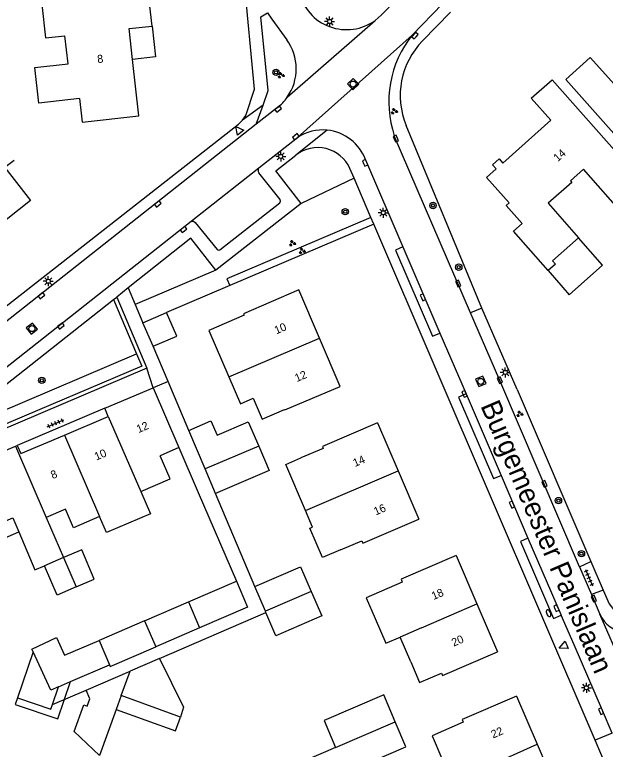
# Model space of a CAD drawing. Extents: x 136000 to 138005, y 398500 to 400500.
# Drawn here: x 137735.1 to 137809, y 398782 to 398873.8 of the extents above; entities that cross this region are included whole.
import ezdxf

# ---------------------------------------------------------------- set-up
doc = ezdxf.new("R2010")
doc.units = 0
for name, color, linetype in [('gg-afsc-erfafscheiding', 7, 'Continuous'), ('gg-afsc-hekwerk', 7, 'Continuous'), ('gg-afsc-muur', 7, 'Continuous'), ('gg-anno-huisnummerreeks BGT', 7, 'Continuous'), ('gg-anno-openbare ruimte label', 7, 'Continuous'), ('gg-bbg-bijgebouw', 7, 'Continuous'), ('gg-bbg-gedigitaliseerde bebouwing', 7, 'Continuous'), ('gg-bbg-gedigitaliseerde bijgebouw', 7, 'Continuous'), ('gg-bbg-hoofdgebouw', 7, 'Continuous'), ('gg-bbg-luifel en loopbrug', 7, 'Continuous'), ('gg-bbg-tussenscheiding', 7, 'Continuous'), ('gg-knt-verharding', 7, 'Continuous'), ('gg-knt-verharding nz', 7, 'Continuous'), ('gt-grn-groengrens', 7, 'Continuous'), ('gt-grn-weggrens', 7, 'Continuous'), ('gt-symb-boom', 7, 'Continuous'), ('gt-symb-brandkraan', 7, 'Continuous'), ('gt-symb-groenvak', 7, 'Continuous'), ('gt-symb-kolk', 7, 'Continuous'), ('gt-symb-lichtmast', 7, 'Continuous'), ('gt-symb-rioolschacht', 7, 'Continuous'), ('gt-symb-tegel verharding', 7, 'Continuous'), ('gt-symb-waterafsluiter', 7, 'Continuous')]:
    doc.layers.add(name, color=color, linetype=linetype)

# ---------------------------------------------------------------- blocks, each defined once
blk = doc.blocks.new('gt0-WAFSL')
at = {"layer": 'gt-symb-waterafsluiter'}
for p, q in [((-0.5, -0.333), (0, 0.667)), ((0, 0.667), (0.5, -0.333)), ((0.5, -0.333), (-0.5, -0.333))]:
    blk.add_line(p, q, dxfattribs=at)
blk = doc.blocks.new('gt0-GRVAK')
at = {"layer": 'gt-symb-groenvak'}
for p, q in [((-0.11, 0.189), (-0.228, 0.24)), ((-0.182, 0.153), (0.088, 0.153)), ((-0.091, 0.211), (-0.156, 0.322)), ((-0.047, 0.214), (-0.047, 0.393)), ((-0.004, 0.211), (0.061, 0.322)), ((0.015, 0.189), (0.133, 0.24)), ((0.262, -0.052), (0.197, 0.059)), ((0.305, -0.049), (0.305, 0.13)), ((0.349, -0.052), (0.414, 0.059)), ((-0.245, -0.228), (-0.363, -0.177)), ((-0.318, -0.264), (-0.047, -0.264)), ((-0.226, -0.206), (-0.291, -0.095)), ((-0.183, -0.203), (-0.183, -0.024)), ((-0.139, -0.206), (-0.074, -0.095)), ((-0.12, -0.228), (-0.002, -0.177)), ((0.243, -0.074), (0.125, -0.023)), ((0.17, -0.11), (0.441, -0.11)), ((0.368, -0.074), (0.486, -0.023))]:
    blk.add_line(p, q, dxfattribs=at)
blk = doc.blocks.new('gt0-KOLK')
at = {"layer": 'gt-symb-kolk'}
blk.add_lwpolyline([(0, 0), (0.375, 0), (0.375, 0.4), (-0.375, 0.4), (-0.375, 0), (0, 0)], dxfattribs=at)
blk = doc.blocks.new('gt0-RS')
at = {"layer": 'gt-symb-rioolschacht'}
blk.add_lwpolyline([(-0.5, -0.5), (0.5, -0.5), (0.5, 0.5), (-0.5, 0.5)], close=True, dxfattribs=at)
blk.add_circle((0, 0), 0.375, dxfattribs=at)
blk = doc.blocks.new('gt0-BOOM')
at = {"layer": 'gt-symb-boom'}
for radius in [0.4, 0.2]:
    blk.add_circle((0, 0), radius, dxfattribs=at)
blk = doc.blocks.new('gt0-LMAST')
at = {"layer": 'gt-symb-lichtmast'}
for p, q in [((-0.182, 0.173), (-0.447, 0.438)), ((-0.005, 0.246), (-0.005, 0.621)), ((0.172, 0.173), (0.437, 0.438)), ((-0.255, -0.004), (-0.63, -0.004)), ((-0.182, -0.181), (-0.447, -0.446)), ((-0.005, -0.254), (-0.005, -0.629)), ((0.437, -0.446), (0.172, -0.181)), ((0.245, -0.004), (0.62, -0.004))]:
    blk.add_line(p, q, dxfattribs=at)
blk.add_circle((-0.005, -0.004), 0.25, dxfattribs=at)
blk = doc.blocks.new('gt0-TEG1')
at = {"layer": 'gt-symb-tegel verharding'}
for p, q in [((-1.125, 0), (1.125, 0)), ((-0.9, -0.25), (-0.9, 0.25)), ((-0.45, -0.25), (-0.45, 0.25)), ((0, -0.25), (0, 0.25)), ((0.45, -0.25), (0.45, 0.25)), ((0.9, -0.25), (0.9, 0.25))]:
    blk.add_line(p, q, dxfattribs=at)
blk = doc.blocks.new('gt0-BR')
at = {"layer": 'gt-symb-brandkraan'}
for centre, radius, start, end in [((-0.244, 0), 0.206, 107.56694, 252.43307), ((0.599, -2.664), 3, 106.89205, 107.56694), ((0, -0.691), 0.938, 73.10799, 106.89205), ((-0.599, -2.664), 3, 72.43309, 73.10799), ((0.244, 0), 0.206, 287.56695, 72.43309), ((0.599, 2.664), 3, 252.43307, 253.10797), ((0, 0.691), 0.938, 253.10797, 286.89206), ((-0.599, 2.664), 3, 286.89206, 287.56695)]:
    blk.add_arc(centre, radius, start, end, dxfattribs=at)

msp = doc.modelspace()

# ---------------------------------------------------------------- linework, layer by layer
at = {"layer": 'gg-afsc-erfafscheiding'}
for p, q in [((137780.034, 398847.619), (137762.017, 398839.982)), ((137758.08, 398814.098), (137762.846, 398803.03)), ((137765.162, 398802.336), (137760.232, 398813.97)), ((137753.222, 398793.371), (137766.53, 398799.12)), ((137739.843, 398787.592), (137744.064, 398789.415))]:
    msp.add_line(p, q, dxfattribs=at)
at = {"layer": 'gg-afsc-hekwerk'}
for p, q in [((137797.931, 398826.979), (137807.16, 398805.464)), ((137807.16, 398805.464), (137808.684, 398801.91))]:
    msp.add_line(p, q, dxfattribs=at)
msp.add_lwpolyline([(137808.684, 398801.91), (137809.432, 398800.189), (137810.149, 398799.284), (137811.65, 398798.236), (137813.481, 398798.666), (137827.526, 398808.434)], dxfattribs=at)
at = {"layer": 'gg-afsc-muur'}
for p, q in [((137762.017, 398839.982), (137754.121, 398836.573)), ((137754.313, 398827.975), (137752.443, 398832.372)), ((137756.912, 398821.866), (137754.313, 398827.975)), ((137755.641, 398819.704), (137758.08, 398814.098))]:
    msp.add_line(p, q, dxfattribs=at)
at = {"layer": 'gg-bbg-bijgebouw'}
for p, q in [((137751.165, 398835.297), (137754.121, 398836.573)), ((137752.443, 398832.372), (137751.165, 398835.297)), ((137758.926, 398817.077), (137756.912, 398821.866)), ((137760.232, 398813.97), (137758.926, 398817.077)), ((137762.846, 398803.03), (137764.23, 398799.784))]:
    msp.add_line(p, q, dxfattribs=at)
at = {"layer": 'gg-bbg-gedigitaliseerde bebouwing'}
for p, q in [((137743.239, 398863.336), (137743.56, 398860.38)), ((137805.625, 398845.904), (137802.36, 398843.03)), ((137759.4, 398834.34), (137761.906, 398828.559)), ((137755.641, 398819.704), (137753.294, 398818.691)), ((137739.056, 398810.977), (137741.214, 398805.968)), ((137745.726, 398811.111), (137742.459, 398809.701)), ((137775.857, 398806.931), (137773.619, 398805.97)), ((137784.635, 398792.952), (137783.311, 398796.036))]:
    msp.add_line(p, q, dxfattribs=at)
for points in [[(137751.83, 398876.57), (137738.539, 398875.069), (137738.989, 398870.908), (137741.416, 398871.17)], [(137743.239, 398863.336), (137738.138, 398862.754), (137737.632, 398867.185), (137741.816, 398867.662), (137741.416, 398871.17)], [(137811.458, 398848.583), (137806.241, 398854.497), (137804.599, 398853.048), (137804.771, 398852.853), (137801.806, 398850.243), (137805.625, 398845.904)], [(137761.906, 398828.559), (137763.367, 398825.19), (137764.956, 398825.869), (137766.061, 398823.281), (137768.868, 398824.48), (137768.896, 398824.414), (137775.81, 398827.36)], [(137780.49, 398822.82), (137773.588, 398819.858), (137773.692, 398819.615), (137770.901, 398818.418)], [(137750.896, 398814.218), (137754.545, 398815.793), (137753.294, 398818.691)], [(137771.484, 398811.832), (137769.006, 398817.604), (137770.901, 398818.418)], [(137730.896, 398813.965), (137732.603, 398809.96), (137734.903, 398810.937), (137735.645, 398809.191)], [(137750.896, 398814.218), (137752.108, 398811.428), (137746.6, 398809.089), (137745.726, 398811.111)], [(137742.459, 398809.701), (137741.463, 398812.014), (137739.056, 398810.977)], [(137773.619, 398805.97), (137772.042, 398809.646), (137772.363, 398809.784), (137771.484, 398811.832)], [(137775.857, 398806.931), (137778.533, 398808.079), (137778.664, 398807.774), (137785.66, 398810.77)], [(137735.645, 398809.191), (137737.661, 398804.445), (137738.864, 398804.956)], [(137790.3, 398806.23), (137783.423, 398803.264), (137783.584, 398802.891), (137779.061, 398800.946), (137780.176, 398798.352)], [(137780.176, 398798.352), (137781.505, 398795.257), (137783.311, 398796.036)], [(137784.635, 398792.952), (137785.744, 398790.373), (137788.466, 398791.544), (137788.607, 398791.215), (137795.48, 398794.18)], [(137797.85, 398788.67), (137791.048, 398785.736), (137791.199, 398785.383), (137787.301, 398783.709), (137788.523, 398780.863)]]:
    msp.add_lwpolyline(points, dxfattribs=at)
at = {"layer": 'gg-bbg-gedigitaliseerde bijgebouw'}
for p, q in [((137756.848, 398800.441), (137762.846, 398803.03)), ((137766.468, 398799.266), (137765.162, 398802.336)), ((137751.356, 398798.07), (137756.848, 398800.441)), ((137764.23, 398799.784), (137758.246, 398797.201)), ((137766.53, 398799.12), (137766.468, 398799.266)), ((137751.356, 398798.07), (137745.671, 398795.616)), ((137758.246, 398797.201), (137752.754, 398794.83)), ((137747.069, 398792.376), (137752.754, 398794.83)), ((137737.422, 398794.197), (137735.475, 398788.432)), ((137742.108, 398790.483), (137746.979, 398792.586)), ((137746.979, 398792.586), (137747.069, 398792.376)), ((137753.222, 398793.371), (137749.552, 398791.786)), ((137744.064, 398789.415), (137749.552, 398791.786)), ((137739.843, 398787.592), (137740.599, 398789.832)), ((137740.599, 398789.832), (137742.108, 398790.483)), ((137744.531, 398788.335), (137744.064, 398789.415)), ((137748.442, 398788.729), (137747.812, 398786.995)), ((137755.851, 398786.038), (137748.442, 398788.729))]:
    msp.add_line(p, q, dxfattribs=at)
for points in [[(137752.443, 398832.372), (137755.386, 398833.643), (137754.121, 398836.573)], [(137756.912, 398821.866), (137759.659, 398823.052), (137760.437, 398821.249), (137764.321, 398822.926), (137765.629, 398819.896)], [(137765.629, 398819.896), (137766.937, 398816.865), (137760.232, 398813.97)], [(137742.794, 398802.301), (137745.082, 398803.286), (137743.503, 398806.954), (137741.214, 398805.968)], [(137742.794, 398802.301), (137740.444, 398801.289), (137738.864, 398804.956)], [(137765.162, 398802.336), (137770.873, 398804.801), (137772.195, 398801.739)], [(137772.195, 398801.739), (137773.517, 398798.676), (137767.789, 398796.204), (137766.53, 398799.12)], [(137737.422, 398794.197), (137737.264, 398794.535), (137740.334, 398795.969), (137741.366, 398793.758), (137745.671, 398795.616)], [(137753.222, 398793.371), (137756.251, 398787.276), (137755.851, 398786.038)], [(137735.475, 398788.432), (137739.651, 398787.022), (137739.843, 398787.592)], [(137742.547, 398784.251), (137743.772, 398787.554), (137744.184, 398787.401), (137744.531, 398788.335)], [(137782.706, 398785.439), (137781.257, 398788.813), (137773.798, 398785.611), (137775.254, 398782.22)], [(137747.812, 398786.995), (137745.715, 398781.223), (137742.547, 398784.251)], [(137775.254, 398782.22), (137767.044, 398778.695), (137768.378, 398775.589), (137784.046, 398782.317), (137782.706, 398785.439)]]:
    msp.add_lwpolyline(points, dxfattribs=at)
at = {"layer": 'gg-bbg-hoofdgebouw'}
for p, q in [((137752.31, 398872.36), (137751.83, 398876.57)), ((137775.81, 398827.36), (137773.235, 398833.39)), ((137746.4, 398824.62), (137752.42, 398827.17)), ((137752.42, 398827.17), (137755.641, 398819.704)), ((137746.82, 398823.6), (137746.4, 398824.62)), ((137741.34, 398821.272), (137746.82, 398823.6)), ((137780.49, 398822.82), (137783.075, 398816.795)), ((137730.838, 398818.033), (137735.214, 398819.894)), ((137735.214, 398819.894), (137735.44, 398819.99)), ((137783.075, 398816.795), (137785.66, 398810.77)), ((137790.3, 398806.23), (137792.89, 398800.205)), ((137792.89, 398800.205), (137795.48, 398794.18)), ((137797.85, 398788.67), (137800.44, 398782.64)), ((137800.44, 398782.64), (137803.03, 398776.61))]:
    msp.add_line(p, q, dxfattribs=at)
for points in [[(137749.867, 398868.205), (137749.45, 398872.06), (137752.31, 398872.36)], [(137743.56, 398860.38), (137750.63, 398861.15), (137749.867, 398868.205)], [(137802.32, 398865.68), (137811.687, 398855.096), (137812.677, 398855.973), (137804.031, 398865.719), (137807.085, 398868.469), (137819.213, 398855.006), (137816.037, 398852.145), (137815.337, 398852.927), (137814.369, 398852.06)], [(137801.82, 398841.82), (137797.48, 398846.75), (137798.56, 398847.72), (137796.58, 398849.97), (137796.94, 398850.28), (137794.1, 398853.46), (137795.31, 398854.54), (137794.85, 398855.05), (137795.69, 398855.8), (137796.15, 398855.27), (137802.15, 398860.64), (137799.71, 398863.37), (137802.32, 398865.68)], [(137735.05, 398855.59), (137733.9, 398854.69), (137737.11, 398850.59), (137731.172, 398845.934)], [(137802.36, 398843.03), (137802.73, 398842.61), (137801.82, 398841.82)], [(137773.235, 398833.39), (137770.66, 398839.42), (137763.73, 398836.43), (137763.83, 398836.25), (137759.4, 398834.34)], [(137735.44, 398819.99), (137735.9, 398818.96), (137741.34, 398821.272)]]:
    msp.add_lwpolyline(points, dxfattribs=at)
at = {"layer": 'gg-bbg-luifel en loopbrug'}
msp.add_line((137731.538, 398807.423), (137735.645, 398809.191), dxfattribs=at)
for points in [[(137752.31, 398872.36), (137752.746, 398868.534), (137749.867, 398868.205)], [(137801.82, 398841.82), (137804.463, 398838.818), (137808.632, 398842.488), (137805.625, 398845.904)], [(137735.475, 398788.432), (137735.204, 398787.63), (137740.536, 398785.829), (137742.108, 398790.483)], [(137747.812, 398786.995), (137755.221, 398784.304), (137755.851, 398786.038)]]:
    msp.add_lwpolyline(points, dxfattribs=at)
at = {"layer": 'gg-bbg-tussenscheiding'}
for p, q in [((137761.906, 398828.559), (137773.235, 398833.39)), ((137746.82, 398823.6), (137750.896, 398814.218)), ((137741.34, 398821.272), (137745.726, 398811.111)), ((137735.214, 398819.894), (137739.056, 398810.977)), ((137765.629, 398819.896), (137758.926, 398817.077)), ((137771.484, 398811.832), (137783.075, 398816.795)), ((137741.214, 398805.968), (137738.864, 398804.956)), ((137741.214, 398805.968), (137742.794, 398802.301)), ((137772.195, 398801.739), (137766.468, 398799.266)), ((137756.848, 398800.441), (137758.246, 398797.201)), ((137785.989, 398797.192), (137792.89, 398800.205)), ((137751.356, 398798.07), (137752.754, 398794.83)), ((137785.989, 398797.192), (137783.311, 398796.036)), ((137745.671, 398795.616), (137746.979, 398792.586)), ((137748.442, 398788.729), (137749.552, 398791.786)), ((137775.254, 398782.22), (137782.706, 398785.439)), ((137793.711, 398779.646), (137800.44, 398782.64))]:
    msp.add_line(p, q, dxfattribs=at)
msp.add_lwpolyline([(137740.599, 398789.832), (137739.652, 398789.422), (137737.422, 398794.197)], dxfattribs=at)
at = {"layer": 'gg-knt-verharding'}
for p, q in [((137784.811, 398871.263), (137788.615, 398875.153)), ((137765.325, 398860.104), (137766.172, 398862.515)), ((137767.979, 398862.202), (137765.325, 398860.104)), ((137763.625, 398860.627), (137764.04, 398861.22)), ((137765.325, 398860.104), (137696.173, 398805.626)), ((137792.122, 398836.535), (137782.584, 398858.67)), ((137765.649, 398854.652), (137770.469, 398858.451)), ((137778.995, 398855.661), (137783.668, 398844.778)), ((137777.555, 398853.394), (137777.042, 398854.59)), ((137779.668, 398848.471), (137777.555, 398853.394)), ((137770.928, 398850.204), (137760.288, 398841.873)), ((137700.598, 398803.386), (137757.205, 398847.998)), ((137780.034, 398847.619), (137779.668, 398848.471)), ((137787.829, 398829.458), (137780.034, 398847.619)), ((137783.668, 398844.778), (137788.285, 398834.027)), ((137749.3, 398839.66), (137750.192, 398837.574)), ((137747.473, 398838.2), (137747.88, 398838.52)), ((137747.88, 398838.52), (137751.66, 398829.63)), ((137728.586, 398823.329), (137747.473, 398838.2)), ((137750.192, 398837.574), (137751.165, 398835.297)), ((137788.285, 398834.027), (137791.55, 398826.424)), ((137751.66, 398829.63), (137729.85, 398820.355)), ((137807.709, 398783.153), (137787.829, 398829.458)), ((137791.55, 398826.424), (137795.923, 398816.242)), ((137795.923, 398816.242), (137799.297, 398808.384)), ((137799.297, 398808.384), (137803.434, 398798.76)), ((137805.734, 398804.823), (137807.16, 398805.464)), ((137805.734, 398804.823), (137807.217, 398801.365)), ((137808.684, 398801.91), (137807.217, 398801.365)), ((137807.217, 398801.365), (137808.279, 398798.887)), ((137860.962, 398659.111), (137807.709, 398783.153))]:
    msp.add_line(p, q, dxfattribs=at)
for points in [[(137764.04, 398861.22), (137765.126, 398864.476), (137762.521, 398891.862), (137760.686, 398913.953)], [(137816.396, 398909.991), (137780.932, 398873.722), (137780.577, 398873.393), (137780.195, 398873.092)], [(137766.172, 398862.515), (137766.804, 398864.317), (137765.913, 398873.55), (137766.744, 398874.046)], [(137766.744, 398874.046), (137767.262, 398873.24), (137769.134, 398870.678)], [(137695.033, 398806.84), (137763.09, 398860.14), (137763.625, 398860.627)], [(137770.928, 398850.204), (137767.756, 398854.274), (137770.269, 398856.265)], [(137757.205, 398847.998), (137757.481, 398847.998), (137757.709, 398847.844), (137760.427, 398844.458), (137760.592, 398844.367), (137760.773, 398844.418), (137768.271, 398850.301), (137768.376, 398850.486), (137768.318, 398850.691), (137765.658, 398854.05)], [(137760.288, 398841.873), (137757.131, 398845.861), (137749.3, 398839.66)], [(137805.734, 398804.823), (137795.637, 398828.377), (137792.122, 398836.535)], [(137809.804, 398784.049), (137808.608, 398786.846), (137805.069, 398795.057), (137803.434, 398798.76)]]:
    msp.add_lwpolyline(points, dxfattribs=at)
for centre, radius, start, end in [((137776.615, 398878.023), 6.093, 193.41717, 305.98014), ((137764.153, 398867.04), 6.168, 324.76261, 36.14493), ((137795.316, 398862.912), 13.42, 141.51534, 198.42717), ((137764.156, 398867.039), 6.165, 308.32511, 324.7563), ((137773.627, 398853.682), 5.72, 84.25869, 123.51), ((137773.628, 398853.681), 5.72, 20.2483, 84.27351), ((137772.993, 398852.747), 4.449, 24.47524, 127.74306), ((137766.044, 398854.357), 0.493, 143.2434, 218.46964), ((137811.783, 398800.431), 3.829, 203.7767, 265.05578)]:
    msp.add_arc(centre, radius, start, end, dxfattribs=at)
at = {"layer": 'gg-knt-verharding nz'}
msp.add_line((137757.205, 398847.998), (137765.649, 398854.652), dxfattribs=at)
for points in [[(137783.668, 398844.778), (137782.744, 398844.381), (137787.353, 398833.626), (137788.285, 398834.027)], [(137791.55, 398826.424), (137790.601, 398826.016), (137794.973, 398815.834), (137795.923, 398816.242)], [(137799.297, 398808.384), (137798.347, 398807.976), (137802.491, 398798.344), (137803.434, 398798.76)]]:
    msp.add_lwpolyline(points, dxfattribs=at)
at = {"layer": 'gt-grn-groengrens'}
for p, q in [((137786.113, 398870.525), (137789.624, 398874.098)), ((137793.543, 398837.147), (137784.068, 398859.951)), ((137777.555, 398853.394), (137770.928, 398850.204)), ((137760.288, 398841.873), (137750.192, 398837.574)), ((137747.473, 398838.2), (137750.35, 398831.432)), ((137793.543, 398837.147), (137792.122, 398836.535)), ((137797.931, 398826.979), (137793.543, 398837.147)), ((137729.02, 398822.308), (137750.35, 398831.432)), ((137750.35, 398831.432), (137751.004, 398829.894)), ((137751.004, 398829.894), (137729.654, 398820.815))]:
    msp.add_line(p, q, dxfattribs=at)
msp.add_lwpolyline([(137779.668, 398848.471), (137761.668, 398840.79), (137762.017, 398839.982)], dxfattribs=at)
msp.add_arc((137793.076, 398863.694), 9.755, 135.5476, 202.56079, dxfattribs=at)
at = {"layer": 'gt-grn-weggrens'}
for p, q in [((137769.191, 398863.481), (137780.195, 398873.092)), ((137784.811, 398871.263), (137770.469, 398858.451)), ((137766.172, 398862.515), (137763.625, 398860.627)), ((137774.199, 398859.373), (137770.269, 398856.265)), ((137749.3, 398839.66), (137747.88, 398838.52)), ((137752.42, 398827.17), (137751.66, 398829.63)), ((137754.313, 398827.975), (137752.42, 398827.17)), ((137746.4, 398824.62), (137735.44, 398819.99)), ((137813.949, 398785.823), (137808.279, 398798.887)), ((137809.804, 398784.049), (137807.709, 398783.153))]:
    msp.add_line(p, q, dxfattribs=at)

# ---------------------------------------------------------------- block references
at = {"layer": 'gt-symb-boom'}
for p in [(137767.795, 398866.6), (137776.453, 398849.184), (137787.425, 398849.958), (137790.641, 398842.256), (137738.52, 398828.114), (137803.107, 398813.086), (137805.978, 398806.457)]:
    msp.add_blockref('gt0-BOOM', p, dxfattribs=at)
at = {"layer": 'gt-symb-brandkraan', "rotation": 113.25875933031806}
msp.add_blockref('gt0-BR', (137801.869, 398799.029), dxfattribs=at)
at = {"layer": 'gt-symb-groenvak'}
for p in [(137768.417, 398866.219), (137782.562, 398861.737), (137769.831, 398845.242), (137771.035, 398844.286), (137798.25, 398823.914)]:
    msp.add_blockref('gt0-GRVAK', p, dxfattribs=at)
at = {"layer": 'gt-symb-kolk'}
for p, rotation in [((137785.325, 398871.048), 47.14809157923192), ((137767.928, 398862.163), -141.49221702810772), ((137770.389, 398858.393), 38.337522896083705), ((137782.587, 398858.243), -66.66595872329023), ((137778.75, 398855.214), -66.66595872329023), ((137753.145, 398850.001), 38.22155685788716), ((137756.339, 398846.807), 38.22155686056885), ((137790.389, 398840.124), -66.66595872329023), ((137738.595, 398838.539), 38.22155685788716), ((137785.984, 398838.406), -66.66595872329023), ((137741.039, 398834.748), 38.22155685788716), ((137795.587, 398828.054), -66.66595872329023), ((137791.168, 398826.34), -66.66595872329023), ((137801.165, 398815.107), -66.66595872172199), ((137797.109, 398812.506), -66.66595872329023), ((137807.34, 398800.766), -66.66595872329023), ((137802.663, 398799.571), -66.66595872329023), ((137808.608, 398786.846), 113.31515287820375)]:
    msp.add_blockref('gt0-KOLK', p, dxfattribs=dict(at, rotation=rotation))
at = {"layer": 'gt-symb-lichtmast'}
for p in [(137774.502, 398872.954), (137768.391, 398856.1), (137781.206, 398849.068), (137739.335, 398840.49), (137796.468, 398829.109), (137806.598, 398789.7)]:
    msp.add_blockref('gt0-LMAST', p, dxfattribs=at)
at = {"layer": 'gt-symb-rioolschacht'}
for p, rotation in [((137777.435, 398865.137), 43.7035699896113), ((137737.284, 398834.572), 38.22155685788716), ((137793.394, 398827.985), -66.66595872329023)]:
    msp.add_blockref('gt0-RS', p, dxfattribs=dict(at, rotation=rotation))
at = {"layer": 'gt-symb-tegel verharding'}
for p, rotation in [((137740.241, 398822.738), 23.025492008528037), ((137806.931, 398803.466), -66.74124066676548)]:
    msp.add_blockref('gt0-TEG1', p, dxfattribs=dict(at, rotation=rotation))
at = {"layer": 'gt-symb-waterafsluiter'}
for p, rotation in [((137763.177, 398859.304), 38.30199383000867), ((137803.826, 398794.929), 113.25875933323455)]:
    msp.add_blockref('gt0-WAFSL', p, dxfattribs=dict(at, rotation=rotation))

# ---------------------------------------------------------------- texts
at = {"layer": 'gg-anno-huisnummerreeks BGT'}
for s, rotation, p in [('8', 6.2, (137745.502, 398867.754)), ('14', 41.8, (137803.014, 398855.374)), ('10', 23.1, (137767.843, 398833.852)), ('12', 23.1, (137770.391, 398827.885)), ('12', 23, (137750.604, 398821.513)), ('10', 23, (137745.343, 398818.083)), ('14', 23.2, (137777.668, 398817.281)), ('8', 23, (137739.882, 398815.763)), ('16', 23.2, (137780.268, 398811.223)), ('18', 23.3, (137787.497, 398800.654)), ('20', 23.3, (137790, 398794.831)), ('22', 23.3, (137794.933, 398783.357))]:
    msp.add_text(s, height=1, rotation=rotation, dxfattribs=at).set_placement(p)
at = {"layer": 'gg-anno-openbare ruimte label'}
msp.add_text('Burgemeester Panislaan', height=2.5, rotation=293.1, dxfattribs=at).set_placement((137793.327, 398824.939))

doc.saveas('drawing.dxf')
